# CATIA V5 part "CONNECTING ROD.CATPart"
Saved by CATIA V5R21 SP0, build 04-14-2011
Part number: Part1.1.1
Bounding box of the stored display mesh (mm): x -13 to 13, y 0 to 192, z -42 to 42
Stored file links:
  G:\CATIA\PROJECT__01\CONNECTING ROD.CATPart
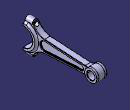
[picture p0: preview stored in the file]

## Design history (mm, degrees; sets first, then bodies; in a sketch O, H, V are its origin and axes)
Body1 (main body)
  Sketch1 on yz-plane, origin (0, 0, 0), H (0, 1, 0), V (0, 0, 1)
    arc A1 centre (0, 0) radius 24 from (0, -24) to (0, 24) ccw
    arc A2 centre (176, 0) radius 16 from (166.7909, -13.084) to (166.7909, 13.084) ccw
    point P1 (176, 0)
    point P2 (0, 24)
    line L1 (0, 24) -> (0, 42)
    point P3 (0, 42)
    line L2 (0, 42) -> (18, 42)
    point P4 (18, 42)
    arc A3 centre (54.9204, 54.7482) radius 39.0593 from (18, 42) to (50, 16) ccw
    point P6 (50, 16)
    point P7 (50, 16)
    line L3 (50, 16) -> (156, 10)
    arc A4 centre (156.9648, 27.0446) radius 17.0719 from (156, 10) to (166.7909, 13.084) ccw
    point P9 (166.7909, 13.084)
    point P10 (156, 10)
    point P11 (156, -10)
    point P12 (50, -16)
    line L4 (50, -16) -> (156, -10)
    point P13 (166.7909, -13.084)
    arc A5 centre (156.9648, -27.0446) radius 17.0719 from (156, -10) to (166.7909, -13.084) cw
    point P15 (50, -16)
    point P16 (18, -42)
    arc A6 centre (54.9204, -54.7482) radius 39.0593 from (18, -42) to (50, -16) cw
    point P18 (0, -42)
    line L5 (0, -42) -> (18, -42)
    point P19 (0, -24)
    line L6 (0, -24) -> (0, -42)
    circle A7 centre (176, 0) radius 10
    radius A1 = 24
    radius A2 = 16
    length L1 = 18
    length L2 = 18
    distance L1 P6 = 50
    distance H P6 = 16
    distance O P1 = 176
    distance P1 P10 H = 20
    distance P1 P10 V = 10
    radius A3 = 39.0593
    radius A7 = 10
    coincidence: P1 H, P2 V, P7 A3, P6 P7, P12 P15
    vertical: L1 V
    horizontal: L2 H
    tangency: A4 A2, A4 L3
    symmetry: P10 P11 H, P7 P12 H, L3 L4 H, P9 P13 H, A4 A5 H, P6 P15 H, P4 P16 H, A3 A6 H, P3 P18 H, L2 L5 H, P2 P19 H, L1 L6 H
  Pad1: profile Sketch1, direction (1, 0, 0), length 8, mirrored extent
  Sketch2 on end face of Pad1, origin (8, 0, 0), H (0, 1, 0), V (0, 0, 1)
    projected arc E1 centre (0, 0) radius 24 from (0, -24) to (0, 24) ccw from edge [face of Pad1 from Sketch1.A1 | end face of Pad1]
    projected circle E2 centre (176, 0) radius 10 from edge [end face of Pad1 | face of Pad1 from Sketch1.A7]
    offset arc E3 centre (0, 0) radius 30 from (0, -30) to (0, 30) ccw from edge [face of Pad1 from Sketch1.A1 | end face of Pad1]
    line L1 (0, 24) -> (0, 30)
    line L2 (0, -24) -> (0, -30)
    circle A1 centre (176, 0) radius 16
    reference projected arc E4 centre (176, 0) radius 16 from (166.7909, -13.084) to (166.7909, 13.084) ccw from edge [face of Pad1 from Sketch1.A2 | end face of Pad1]
    vertical: L1 V, L2 V
    coincidence: A1 E4
  Pad2: profile Sketch2, direction (1, 0, 0), length 5
  Mirror1: of Pad2, about yz-plane
  TritangentFillet1: Face1 end face of Pad1, Face2 start face of Pad1, RemoveFace face of Pad1 from Sketch1.L2
  TritangentFillet2: Face1 end face of Pad1, Face2 start face of Pad1, RemoveFace face of Pad1 from Sketch1.L5
  Fillet1: radius 5, on edge [end face of Pad1 | face of Pad2 from Sketch2.E3]; edge [face of Mirror1 | start face of Pad1]
  Fillet2: radius 3, on edge [end face of Pad1 | face of Pad2 from Sketch2.A1]; edge [face of Mirror1 | start face of Pad1]
  Sketch3 on face of Mirror1, origin (0, 0, 0), H (1, 0, 0), V (0, 0, 1)
    circle A1 centre (0, 34) radius 2.5
    reference projected arc E1 centre (0, 34) radius 8 from (8, 34) to (-8, 34) ccw from edge [face of Mirror1 | face of TritangentFillet1]
    circle A2 centre (0, -34) radius 2.5
    radius A1 = 2.5
    concentricity: A1 E1
    symmetry: A1 A2 H
  Pocket1: profile Sketch3, direction (0, 1, 0), through (limit type 6)
  Plane1: type Offset, RefPlane face of Mirror1, Offset 16
  Sketch4 on Plane1, origin (0, 16, 0), H (-1, 0, 0), V (0, 0, 1)
    circle A1 centre (0, 34) radius 5
    reference projected arc E1 centre (0, 34) radius 8 from (8, 34) to (-8, 34) ccw from edge [face of Pad1 from Sketch1.A3 | face of TritangentFillet1]
    circle A2 centre (0, -34) radius 5
    radius A1 = 5
    concentricity: A1 E1
    symmetry: A1 A2 H
  Pocket2: profile Sketch4, direction (0, 1, 0), through (limit type 6)
  Chamfer1: length 1, angle 45, on edge [end face of Pad2 | face of Mirror1]; edge [face of Mirror1 | face of Mirror1] (x2); edge [face of Mirror1 | end face of Pad2]
  Sketch5 on end face of Pad1, origin (8, 0, 0), H (0, 1, 0), V (0, 0, 1)
    reference projected circle E1 centre (176, 0) radius 16 from edge [face of Pad2 from Sketch2.A1 | end face of Pad2]
    axis line L1 (0, 0) -> (176, 0)
    point P1 (176, 0)
    offset line E2 (155.7174, 5.008) -> (49.7174, 11.008) from edge [face of Pad1 from Sketch1.L3 | end face of Pad1]
    offset line E3 (146.3136, 5.5403) -> (50.6202, 10.9569) from edge [face of Pad1 from Sketch1.L3 | end face of Pad1]
    offset line E4 (49.7174, -11.008) -> (155.7174, -5.008) from edge [face of Pad1 from Sketch1.L4 | end face of Pad1]
    offset line E5 (50.6202, -10.9569) -> (146.3136, -5.5403) from edge [face of Pad1 from Sketch1.L4 | end face of Pad1]
    arc A1 centre (146, 0) radius 5.5492 from (146.3136, -5.5403) to (146.3136, 5.5403) ccw
    point P6 (146, 0)
    arc A2 centre (50, 0) radius 10.9744 from (50.6202, 10.9569) to (50.6202, -10.9569) ccw
    point P7 (50, 0)
    point P8 (50.6202, 10.9569)
    point P9 (50.6202, -10.9569)
    point P10 (50.6202, 10.9569)
    point P11 (146.3136, 5.5403)
    point P12 (146.3136, -5.5403)
    distance P6 P1 = 30
    distance P7 O = 50
    concentricity: P1 E1
    horizontal: L1 H
    coincidence: P6 L1, P7 L1, A2 P8, P8 E2, E4 P9, E2 P10, E2 P11, E4 P12
    tangency: A1 E2, A2 E2
  Pocket3: profile Sketch5, direction (-1, 0, 0), length 3
  Mirror2: of Pocket3, about yz-plane
  Fillet3: radius 1, on edge [face of Pad1 from Sketch1.L3 | end face of Pad1]; edge [end face of Pad1 | face of Pocket3 from Sketch5.E3]; edge [face of Pocket3 from Sketch5.A2 | end face of Pocket3]; edge [face of Pad1 from Sketch1.A6 | end face of Pad1]; edge [face of Pad1 from Sketch1.L4 | end face of Pad1]; edge [face of Pad1 from Sketch1.A3 | end face of Pad1]; edge [start face of Pad1 | face of Pad1 from Sketch1.L3]; edge [start face of Pad1 | face of Pad1 from Sketch1.L4]
  Fillet4: radius 1, on face of Mirror2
